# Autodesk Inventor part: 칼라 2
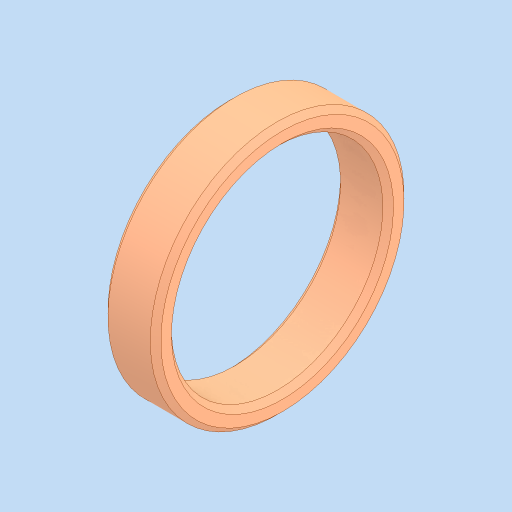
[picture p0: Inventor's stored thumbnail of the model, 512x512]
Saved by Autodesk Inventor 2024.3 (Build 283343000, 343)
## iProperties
Created: 2025-11
Part Number: 칼라 2
Material: 강철, 연강
Document SubType Name: Modeling
Designer: PC2-03
Density: 7.85 g/cm^3
Appearance: 기본값
Author: jhkim
Sending System: Autodesk Inventor 2026
Preprocessor: ST-DEVELOPER v20.1
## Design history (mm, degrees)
feature "솔리드1"
node "솔리드2"
